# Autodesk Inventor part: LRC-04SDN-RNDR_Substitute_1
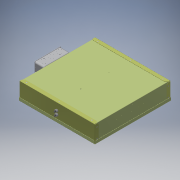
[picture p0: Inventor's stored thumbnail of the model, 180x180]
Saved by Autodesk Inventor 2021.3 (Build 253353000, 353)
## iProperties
Part Number: LRC-04SDN-RNDR_Substitute_1
Material: Generic
Document SubType Name: Modeling
Designer: JChurch
Manufacturer: Standard
Standards Organization: Custom
Density: 1 g/cm^3
Appearance: Smooth - Black
Author: JChurch
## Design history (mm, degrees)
derived "LRC-04SDN-RNDR.iam"
body "Solid9"
node "830520-00-00.ipt:1"
node "885000-00-00.iam:1::830000-00-00.ipt:1"
body "Solid10"
node "885000-00-00.iam:1::509424-00-00.ipt:1"
body "Solid11"
node "885000-00-00.iam:1::830593-00-00.ipt:1"
body "Solid12"
node "885000-00-00.iam:1::506002-00-00.ipt:1"
body "Solid13"
node "885000-00-00.iam:1::506002-00-00.ipt:2"
body "Solid14"
node "885000-00-00.iam:1::506002-00-00.ipt:3"
body "Solid15"
node "885000-00-00.iam:1::506002-00-00.ipt:4"
body "Solid16"
node "885000-00-00.iam:1::506002-00-00.ipt:5"
body "Solid17"
node "885000-00-00.iam:1::506002-00-00.ipt:6"
body "Solid18"
node "885000-00-00.iam:1::506002-00-00.ipt:7"
body "Solid19"
node "885000-00-00.iam:1::506002-00-00.ipt:8"
body "Solid20"
node "885000-00-00.iam:1::506002-00-00.ipt:9"
body "Solid21"
node "885000-00-00.iam:1::506002-00-00.ipt:10"
body "Solid22"
node "885000-00-00.iam:1::506002-00-00.ipt:11"
body "Solid23"
node "885000-00-00.iam:1::506002-00-00.ipt:12"
body "Solid24"
node "885000-00-00.iam:1::506002-00-00.ipt:13"
body "Solid25"
node "885000-00-00.iam:1::506002-00-00.ipt:14"
body "Solid26"
node "885000-00-00.iam:1::500027-00-00.ipt:1"
body "Solid27"
node "885000-00-00.iam:1::500027-00-00.ipt:2"
body "Solid28"
node "885000-00-00.iam:1::502116-00-00.ipt:1"
body "Solid29"
node "885000-00-00.iam:1::502116-00-00.ipt:2"
body "Solid30"
node "885000-00-00.iam:1::501030-00-00.ipt:1"
body "Solid31"
node "885000-00-00.iam:1::501030-00-00.ipt:2"
body "Solid32"
node "885000-00-00.iam:1::501030-00-00.ipt:3"
body "Solid33"
node "885000-00-00.iam:1::501030-00-00.ipt:4"
body "Solid34"
node "885000-00-00.iam:1::500027-00-00.ipt:3"
body "Solid35"
node "885000-00-00.iam:1::500027-00-00.ipt:4"
body "Solid36"
node "885000-00-00.iam:1::501030-00-00.ipt:5"
body "Solid37"
node "885000-00-00.iam:1::500027-00-00.ipt:5"
body "Solid38"
node "885000-00-00.iam:1::501030-00-00.ipt:6"
body "Solid39"
node "885000-00-00.iam:1::500027-00-00.ipt:6"
body "Solid40"
node "885000-00-00.iam:1::830593-00-00.ipt:2"
body "Solid41"
node "885000-00-00.iam:1::507032-00-00.ipt:1"
body "Solid42"
node "885000-00-00.iam:1::640042-00-03.ipt:1"
body "Solid43"
node "885000-00-00.iam:1::501030-00-00.ipt:9"
body "Solid44"
node "885000-00-00.iam:1::501030-00-00.ipt:10"
body "Solid45"
node "885000-00-00.iam:1::501030-00-00.ipt:11"
body "Solid46"
node "885000-00-00.iam:1::501030-00-00.ipt:12"
body "Solid47"
node "885000-00-00.iam:1::503031-00-00.ipt:1"
body "Solid48"
node "885000-00-00.iam:1::503031-00-00.ipt:2"
body "Solid49"
node "885000-00-00.iam:1::509425-00-00.ipt:1"
body "Solid50"
node "750031-00-XX.iam:1::710017-00-XX.ipt:1"
body "Solid51"
node "750031-00-XX.iam:1::507035-01-38.ipt:1"
body "Solid52"
node "750031-00-XX.iam:1::507035-01-38.ipt:2"
body "Solid53"
node "725377-00-00.ipt:1"
body "Solid54"
other parameters: "d15" = 61.595, "d16" = 9.525, "d17" = 9.525, "d35" = 5.08
